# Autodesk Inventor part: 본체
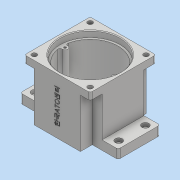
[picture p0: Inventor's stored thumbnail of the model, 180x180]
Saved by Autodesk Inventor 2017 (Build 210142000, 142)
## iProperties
Part Number: 본체
Material: 일반
Document SubType Name: Modeling
Designer: user
Density: 1 g/cm^3
Appearance: 기본값
Mass: 324.618 g
Surface Area: 793.621 cm^2
Volume: 324.618 cm^3
Author: user
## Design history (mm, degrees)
sketch "스케치11"
  geometry: L1 (-70, -30)-(70, -30); L2 (70, -30)-(70, 30); L3 (70, 30)-(-70, 30); L4 (-70, 30)-(-70, -30); L5 (-70, -30)-(70, 30); L6 (70, -30)-(-70, 30); L7 (-33, 47)-(33, 47); L8 (33, 47)-(33, -47); L9 (33, -47)-(-33, -47); L10 (-33, -47)-(-33, 47); L11 (-33, 47)-(33, -47); L12 (33, 47)-(-33, -47); 1 further point
  constraints: 24 end point, 4 midpoint, 4 parallel, 2 horizontal, 2 perpendicular
  dimensions: "d37" = 140 distance of L3.end L2.end; "d38" = 60 distance of L2.end L1.end; "d39" = 66 distance of L8.end L9.end; "d40" = 94 distance of L7.end L8.end
extrude "돌출10" new body sketch "스케치11" distance "d41" = 13; taper "d42" = 0 deg
sketch "스케치12"
  geometry: L1 (-47, 30)-(47, 30); L2 (47, 30)-(47, -30); L3 (47, -30)-(-47, -30); L4 (-47, -30)-(-47, 30); L5 (-47, 30)-(47, -30); L6 (47, 30)-(-47, -30); L7 (-33, 47)-(33, 47); L8 (33, 47)-(33, -47); L9 (33, -47)-(-33, -47); L10 (-33, -47)-(-33, 47); L11 (-33, 47)-(33, -47); L12 (33, 47)-(-33, -47); 1 further point
  constraints: 24 end point, 4 midpoint, 4 parallel, 2 horizontal, 2 perpendicular
  dimensions: "d43" = 94 distance of L2.end L3.end; "d44" = 60 distance of L1.end L2.end; "d45" = 66 distance of L8.end L9.end; "d46" = 94 distance of L7.end L8.end
extrude "돌출11" join sketch "스케치12" distance "d47" = 57; taper "d48" = 0 deg
sketch "스케치13"
  geometry: L1 (-47, -47)-(47, -47); L2 (47, -47)-(47, 47); L3 (47, 47)-(-47, 47); L4 (-47, 47)-(-47, -47); L5 (-47, -47)-(47, 47); L6 (47, -47)-(-47, 47); 1 further point
  constraints: 12 end point, 2 midpoint, 2 parallel, 1 horizontal, 1 perpendicular
  dimensions: "d49" = 94 distance of L3.end L2.end; "d50" = 94 distance of L2.end L1.end
extrude "돌출12" join sketch "스케치13" distance "d51" = 10; taper "d52" = 0 deg
sketch "스케치14"
  geometry: C1 r 43 at (0, 0); 1 further point
  constraints: 1 centre point, 1 coincident
  dimensions: "d53" = 86 diameter of C1
extrude "돌출13" cut sketch "스케치14" distance "d54" = 9; taper "d55" = 0 deg
sketch "스케치15"
  geometry: C1 r 40 at (0, 0); 1 further point
  constraints: 1 centre point, 1 coincident
  dimensions: "d56" = 80 diameter of C1
extrude "돌출14" cut sketch "스케치15" distance "d57" = 62; taper "d58" = 0 deg
sketch "스케치16"
  geometry: C1 r 27.5 at (0, -11); 1 further point
  constraints: 1 centre point, 1 vertical alignment
  dimensions: "d59" = 55 diameter of C1; "d60" = 11 distance of point (0, 0) C1.centre
extrude "돌출15" join sketch "스케치16" distance "d61" = 7; taper "d62" = 0 deg
sketch "스케치17"
  geometry: C1 r 21 at (0, -11); C2 r 15 at (0, 20); 1 further point
  constraints: 2 centre point, 2 vertical alignment
  dimensions: "d63" = 42 diameter of C1; "d64" = 30 diameter of C2; "d65" = 11 distance of point (0, 0) C1.centre; "d66" = 20 distance of C2.centre point (0, 0)
extrude "돌출16" join sketch "스케치17" distance "d67" = 7; taper "d68" = 0 deg
sketch "스케치22"
  geometry: C1 r 11 at (0, 20); A1 r 15 centre (0, 20) between (8.978, 7.984) and (-8.978, 7.984) reference; 1 further point
  constraints: 1 centre point, 1 concentric
  dimensions: "d78" = 22 diameter of C1
extrude "돌출20" cut sketch "스케치22" distance "d79" = 7; taper "d80" = 0 deg
sketch "스케치23"
  geometry: C1 r 9.5 at (0, 0); C2 r 11 at (0, 0) reference; 1 further point
  constraints: 1 centre point, 1 concentric
  dimensions: "d81" = 19 diameter of C1
extrude "돌출21" cut sketch "스케치23" distance "d82" = 3; taper "d83" = 0 deg
sketch "스케치24"
  geometry: 2 further points
  dimensions: "d84" = 60 horizontal distance of point (-60, -19) point (0, 0); "d85" = 19 vertical distance of point (0, 0) point (-60, -19)
hole "구멍1" sketch "스케치24" at (-60, -19) diameter "d86" = 4.5; stored, may be unused: countersink angle "d90" = 90 deg, drill point angle "d92" = 0 deg; dims "d87" = 6, "d88" = 10, "d89" = 5, "d91" = 13
sketch "스케치25"
  geometry: C1 r 3.5 at (40, -40); 1 further point
  constraints: 1 centre point
  dimensions: "d99" = 7 diameter of C1; "d100" = 40 horizontal distance of C1.centre point (0, 0); "d101" = 40 horizontal distance of point (0, 0) C1.centre
extrude "돌출22" cut sketch "스케치25" stored distance "d102" = 3; taper "d103" = 0 deg
sketch "스케치26"
  geometry: A1 r 4 centre (36, 0) between (36.19, 3.995) and (36.19, -3.995); A2 r 40 centre (0, 0) between (39.279, 7.559) and (39.279, -7.559) reference; A3 r 3 centre (36.333, 6.992) between (36.19, 3.995) and (39.279, 7.559); A4 r 3 centre (36.333, -6.992) between (39.279, -7.559) and (36.19, -3.995); 1 further point
  constraints: 8 point on circle, 4 tangent, 3 centre point, 1 horizontal alignment
  dimensions: "d110" = 8 diameter of A1; "d111" = 36 distance of point (0, 0) A1.centre; "d124" = 3 radius of A3; "d125" = 3 radius of A4
extrude "돌출23" join sketch "스케치26" stored distance "d114" = 3; taper "d115" = 0 deg
node "작업 평면1"
sketch "스케치27"
  geometry: 2 further points
  constraints: 1 horizontal alignment
  dimensions: "d116" = 36 distance of point (0, 0) point (36, 0)
hole "구멍2" sketch "스케치27" at (36, 0) diameter "d117" = 3.242; stored, may be unused: countersink angle "d121" = 90 deg, drill point angle "d123" = 118 deg; dims "d118" = 7, "d119" = 10, "d120" = 5, "d122" = 9
sketch "스케치28"
  geometry: L1 (66, 0)-(0, 0) reference; L2 (-14, 80)-(80, 80) reference; 3 further points
  constraints: 1 midpoint, 1 vertical alignment, 1 other
  dimensions: "d126" = 40 distance from line of L2 point (33, 40)
feature "엠보싱1" sketch "스케치28" dims "d37" = 140, "d38" = 60, "d45" = 66, "d46" = 94, "d127" = 0.5, "d128" = 0
fillet "모깎기1" dims "d129" = 3
fillet "모깎기2" dims "d130" = 3
chamfer "모따기2" distance "d134" = 1; stored, may be unused: second distance "d135" = 2, angle "d136" = 30 deg
chamfer "모따기3" distance "d137" = 1; stored, may be unused: second distance "d138" = 2, angle "d139" = 30 deg
fillet "모깎기3" dims "d140" = 3
fillet "모깎기4" dims "d141" = 3
sketch "스케치29"
  geometry: C1 r 17.5 at (0, -11); A1 r 21 centre (0, -11) between (-12.163, 6.119) and (12.163, 6.119) reference; 1 further point
  constraints: 1 centre point, 1 concentric
  dimensions: "d142" = 35 diameter of C1
extrude "돌출24" cut sketch "스케치29" distance "d143" = 10; taper "d144" = 0 deg
sketch "스케치30"
  geometry: C1 r 16 at (0, 0); C2 r 27.5 at (0, 0) reference; 1 further point
  constraints: 1 centre point, 1 concentric
  dimensions: "d145" = 32 diameter of C1
extrude "돌출25" cut sketch "스케치30" distance "d146" = 8.3; taper "d147" = 0 deg
sketch "스케치31"
  geometry: C1 r 12.5 at (0, 0); C2 r 16 at (0, 0) reference; 1 further point
  constraints: 1 centre point, 1 concentric
  dimensions: "d148" = 25 diameter of C1
extrude "돌출26" cut sketch "스케치31" stored distance "d149" = 8.3; taper "d150" = 0 deg
chamfer "모따기4" distance "d151" = 0.8; stored, may be unused: second distance "d152" = 2, angle "d153" = 30 deg
chamfer "모따기5" distance "d154" = 1; stored, may be unused: second distance "d155" = 2, angle "d156" = 30 deg
node "솔리드3"
pattern_linear "직사각형 패턴1" dims "d95" = 120, "d98" = -38
pattern_linear "직사각형 패턴2" dims "d106" = -80, "d109" = 80
mirror "미러1"
